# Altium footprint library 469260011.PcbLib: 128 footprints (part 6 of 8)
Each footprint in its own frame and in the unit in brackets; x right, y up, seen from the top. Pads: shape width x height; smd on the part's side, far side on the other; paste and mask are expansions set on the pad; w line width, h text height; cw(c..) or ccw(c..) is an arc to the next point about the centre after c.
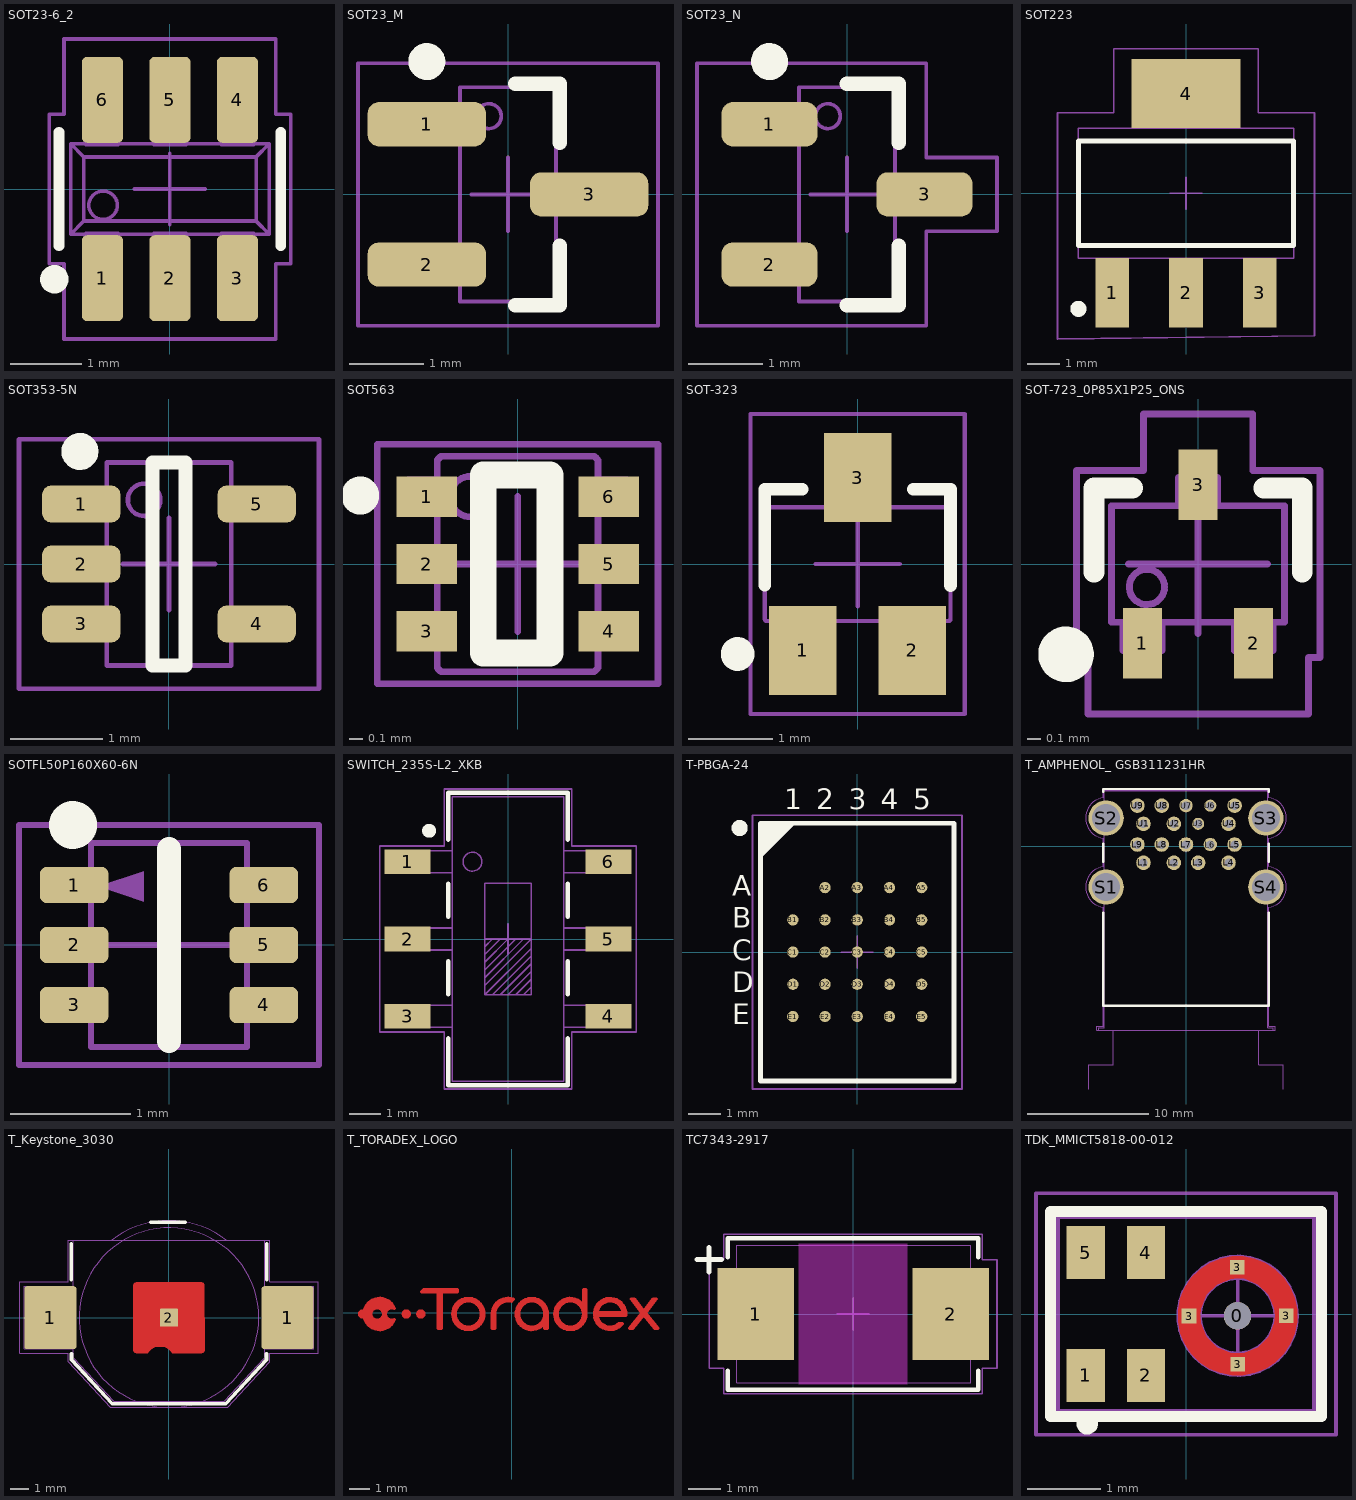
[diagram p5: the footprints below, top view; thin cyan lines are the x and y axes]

## SOT23-6_2 [mm]
pads (6):
  rrect25% 0.58x1.21 smd: 1(-0.95,-1.255) 2(0,-1.255) 3(0.95,-1.255) 4(0.95,1.255) 5(0,1.255) 6(-0.95,1.255)
Top Overlay:
  circle w0.2: c-1.626,-1.27 r0.1
  lines w0.15: -1.56,-0.8 -1.56,0.8 ; 1.56,-0.8 1.56,0.8
Top Assembly:
  circle w0.05: c-0.94,-0.229 r0.2
  lines w0.05: -1.181,-0.635 -1.397,-0.635 ; -1.181,0.635 -1.397,0.635 ; -0.724,-0.635 -0.229,-0.635 ; -0.724,0.635 -0.229,0.635 ; 0.229,-0.635 0.724,-0.635 ; 0.229,0.635 0.724,0.635 ; 1.181,-0.635 1.397,-0.635 ; 1.181,0.635 1.397,0.635 ; -1.397,-0.635 -1.397,0.635 ; -1.397,-0.635 -1.212,-0.45 ; -1.397,0.635 -1.212,0.45 ; -1.212,-0.45 -1.212,0.45 ; -1.212,-0.45 1.212,-0.45 ; -1.212,0.45 1.212,0.45 ; -1.181,-1.003 -0.724,-1.003 ; -1.181,-1.003 -1.181,-1.206 -0.724,-1.206 -0.724,-1.003 ; -1.181,-1.003 -1.181,-0.927 ; -1.181,-0.927 -1.181,-0.648 ; -1.181,-0.927 -0.724,-0.927 ; -1.181,-0.648 -0.724,-0.648 ; -1.181,-0.648 -1.181,-0.626 -0.724,-0.626 -0.724,-0.648 ; -1.181,0.66 -0.724,0.66 ; -1.181,0.66 -1.181,0.94 ; -1.181,0.66 -1.181,0.626 -0.724,0.626 -0.724,0.66 ; -1.181,0.94 -1.181,1.016 ; -1.181,0.94 -0.724,0.94 ; -1.181,1.016 -0.724,1.016 ; -1.181,1.016 -1.181,1.219 -0.724,1.219 -0.724,1.016 ; -0.724,-1.003 -0.724,-0.927 ; -0.724,-0.927 -0.724,-0.648 ; -0.724,0.66 -0.724,0.94 ; -0.724,0.94 -0.724,1.016 ; -0.229,-1.003 0.229,-1.003 ; -0.229,-1.003 -0.229,-1.206 0.229,-1.206 0.229,-1.003 ; -0.229,-1.003 -0.229,-0.927 ; -0.229,-0.927 -0.229,-0.648 ; -0.229,-0.927 0.229,-0.927 ; -0.229,-0.648 0.229,-0.648 ; -0.229,-0.648 -0.229,-0.626 0.229,-0.626 0.229,-0.648 ; -0.229,0.66 0.229,0.66 ; -0.229,0.66 -0.229,0.94 ; -0.229,0.66 -0.229,0.626 0.229,0.626 0.229,0.66 ; -0.229,0.94 -0.229,1.016 ; -0.229,0.94 0.229,0.94 ; -0.229,1.016 0.229,1.016 ; -0.229,1.016 -0.229,1.219 0.229,1.219 0.229,1.016 ; 0.229,-1.003 0.229,-0.927 ; 0.229,-0.927 0.229,-0.648 ; 0.229,0.66 0.229,0.94 ; 0.229,0.94 0.229,1.016 ; 0.724,-1.003 1.181,-1.003 ; 0.724,-1.003 0.724,-1.206 1.181,-1.206 1.181,-1.003 ; 0.724,-1.003 0.724,-0.927 ; 0.724,-0.927 0.724,-0.648 ; 0.724,-0.927 1.181,-0.927 ; 0.724,-0.648 1.181,-0.648 ; 0.724,-0.648 0.724,-0.626 1.181,-0.626 1.181,-0.648 ; 0.724,0.66 1.181,0.66 ; 0.724,0.66 0.724,0.94 ; 0.724,0.66 0.724,0.626 1.181,0.626 1.181,0.66 ; 0.724,0.94 0.724,1.016 ; 0.724,0.94 1.181,0.94 ; 0.724,1.016 1.181,1.016 ; 0.724,1.016 0.724,1.219 1.181,1.219 1.181,1.016 ; 1.181,-1.003 1.181,-0.927 ; 1.181,-0.927 1.181,-0.648 ; 1.181,0.66 1.181,0.94 ; 1.181,0.94 1.181,1.016 ; 1.212,-0.45 1.212,0.45 ; 1.212,-0.45 1.397,-0.635 ; 1.212,0.45 1.397,0.635 ; 1.397,-0.635 1.397,0.635
  text ".Designator" at -2.252,-0.226 h1
Top Courtyard:
  lines w0.05: -0.5,0 0.5,0 ; 0,-0.5 0,0.5 ; -1.7,-1.05 -1.7,1.05 -1.49,1.05 -1.49,2.11 1.49,2.11 1.49,1.05 1.7,1.05 1.7,-1.05 1.49,-1.05 1.49,-2.11 -1.49,-2.11 -1.49,-1.05 -1.7,-1.05
3D body "TPD4E001DBVR.step": height 1.45, standoff 0, extent -1.45,-1.4 1.45,1.4

## SOT23_M [mm]
height 2.5
pads (3):
  rrect50% 1.6x0.6 smd: 1(-1.1,0.95) 2(-1.1,-0.95) 3(1.1,0)
Top Overlay:
  circle w0.25: c-1.1,1.8 r0.125
  lines w0.2: 0.1,-1.5 0.7,-1.5 0.7,-0.7 ; 0.1,1.5 0.7,1.5 0.7,0.7
Top Assembly:
  circle w0.05: c-0.26,1.06 r0.169
  lines w0.05: -1.19,-1.19 -1.4,-1.19 -1.4,-0.71 -1.19,-0.71 ; -1.19,-1.19 -1.19,-0.71 ; -1.19,-1.19 -1.099,-1.19 ; -1.19,-0.71 -1.099,-0.71 ; -1.19,0.71 -1.19,1.19 ; -1.19,0.71 -1.4,0.71 -1.4,1.19 -1.19,1.19 ; -1.19,0.71 -1.099,0.71 ; -1.19,1.19 -1.099,1.19 ; -1.099,-1.19 -1.074,-1.19 ; -1.099,-1.19 -1.099,-0.71 ; -1.099,-0.71 -1.074,-0.71 ; -1.099,0.71 -1.099,1.19 ; -1.099,0.71 -1.074,0.71 ; -1.099,1.19 -1.074,1.19 ; -1.074,-1.19 -1.074,-0.71 ; -1.074,-1.19 -0.825,-1.19 ; -1.074,-0.71 -0.825,-0.71 ; -1.074,0.71 -1.074,1.19 ; -1.074,0.71 -0.825,0.71 ; -1.074,1.19 -0.825,1.19 ; -0.825,-1.19 -0.65,-1.19 ; -0.825,-1.19 -0.825,-0.71 ; -0.825,-0.71 -0.65,-0.71 ; -0.825,0.71 -0.825,1.19 ; -0.825,0.71 -0.65,0.71 ; -0.825,1.19 -0.65,1.19 ; -0.65,-1.19 -0.65,-0.71 ; -0.65,-1.19 -0.65,-1.45 0.65,-1.45 0.65,-0.24 ; -0.65,-0.71 -0.65,0.71 ; -0.65,0.71 -0.65,1.19 ; -0.65,1.19 -0.65,1.45 0.65,1.45 0.65,0.24 ; 0.65,-0.24 0.65,0.24 ; 0.65,-0.24 0.825,-0.24 ; 0.65,0.24 0.825,0.24 ; 0.825,-0.24 0.825,0.24 ; 0.825,-0.24 1.074,-0.24 ; 0.825,0.24 1.074,0.24 ; 1.074,-0.24 1.074,0.24 ; 1.074,-0.24 1.099,-0.24 ; 1.074,0.24 1.099,0.24 ; 1.099,-0.24 1.099,0.24 ; 1.099,-0.24 1.19,-0.24 ; 1.099,0.24 1.19,0.24 ; 1.19,-0.24 1.19,0.24 ; 1.19,-0.24 1.4,-0.24 1.4,0.24 1.19,0.24
  text ".Designator" at -0.226,2.252 h1
Top Courtyard:
  lines w0.05: -0.5,0 0.5,0 ; 0,-0.5 0,0.5 ; -2.032,-1.778 -2.032,1.778 2.032,1.778 2.032,-1.778 -2.032,-1.778
3D body "User Library-SOT23-3.step": height 1.3, standoff 0, extent -1.4,-1.45 1.4,1.45

## SOT23_N [mm] "SOT23, 3-Leads, Body 2.9x1.3mm, Pitch 0.95mm, Lead Span 2.3mm, IPC Medium Density"
height 1.1
pads (3):
  rrect50% 1.3x0.6 smd: 1(-1.05,0.95) 2(-1.05,-0.95) 3(1.05,0)
Top Overlay:
  circle w0.25: c-1.05,1.8 r0.125
  lines w0.2: 0,-1.5 0.7,-1.5 0.7,-0.7 ; 0,1.5 0.7,1.5 0.7,0.7
Top Assembly:
  circle w0.05: c-0.26,1.06 r0.169
  lines w0.05: -1.19,-1.19 -1.099,-1.19 ; -1.19,-1.19 -1.4,-1.19 -1.4,-0.71 -1.19,-0.71 ; -1.19,-1.19 -1.19,-0.71 ; -1.19,-0.71 -1.099,-0.71 ; -1.19,0.71 -1.099,0.71 ; -1.19,0.71 -1.4,0.71 -1.4,1.19 -1.19,1.19 ; -1.19,0.71 -1.19,1.19 ; -1.19,1.19 -1.099,1.19 ; -1.099,-1.19 -1.074,-1.19 ; -1.099,-1.19 -1.099,-0.71 ; -1.099,-0.71 -1.074,-0.71 ; -1.099,0.71 -1.074,0.71 ; -1.099,0.71 -1.099,1.19 ; -1.099,1.19 -1.074,1.19 ; -1.074,-1.19 -0.825,-1.19 ; -1.074,-1.19 -1.074,-0.71 ; -1.074,-0.71 -0.825,-0.71 ; -1.074,0.71 -0.825,0.71 ; -1.074,0.71 -1.074,1.19 ; -1.074,1.19 -0.825,1.19 ; -0.825,-1.19 -0.65,-1.19 ; -0.825,-1.19 -0.825,-0.71 ; -0.825,-0.71 -0.65,-0.71 ; -0.825,0.71 -0.65,0.71 ; -0.825,0.71 -0.825,1.19 ; -0.825,1.19 -0.65,1.19 ; -0.65,-1.19 -0.65,-1.45 0.65,-1.45 0.65,-0.24 ; -0.65,-1.19 -0.65,-0.71 ; -0.65,-0.71 -0.65,0.71 ; -0.65,0.71 -0.65,1.19 ; -0.65,1.19 -0.65,1.45 0.65,1.45 0.65,0.24 ; 0.65,-0.24 0.65,0.24 ; 0.65,-0.24 0.825,-0.24 ; 0.65,0.24 0.825,0.24 ; 0.825,-0.24 1.074,-0.24 ; 0.825,-0.24 0.825,0.24 ; 0.825,0.24 1.074,0.24 ; 1.074,-0.24 1.099,-0.24 ; 1.074,-0.24 1.074,0.24 ; 1.074,0.24 1.099,0.24 ; 1.099,-0.24 1.19,-0.24 ; 1.099,-0.24 1.099,0.24 ; 1.099,0.24 1.19,0.24 ; 1.19,-0.24 1.4,-0.24 1.4,0.24 1.19,0.24 ; 1.19,-0.24 1.19,0.24
  text ".Designator" at -0.226,2.252 h1
Top Courtyard:
  lines w0.05: -0.5,0 0.5,0 ; 0,-0.5 0,0.5 ; -2.032,-1.778 -2.032,1.778 1.072,1.778 1.072,0.5 2.032,0.5 2.032,-0.5 1.072,-0.5 1.072,-1.778 -2.032,-1.778
3D body "User Library-SOT23-3.step": height 1.3, standoff 0, extent -1.4,-1.45 1.4,1.45

## SOT223 [mm]
height 2
pads (4):
  rect 1.05x2.15 smd: 1(-2.3,-3.1) 2(0,-3.1) 3(2.3,-3.1)
  rect 3.4x2.15 smd: 4(0,3.1)
Top Overlay:
  circle w0.25: c-3.35,-3.602 r0.125
  lines w0.15: -3.35,-1.625 -3.35,1.625 3.35,1.625 3.35,-1.625 -3.35,-1.625
Top Assembly:
  lines w0.05: -2.616,-2.025 -2.616,-3.602 -2,-3.602 -2,-2.025 ; -1.45,2.025 -1.45,3.602 1.45,3.602 1.45,2.025 ; -0.316,-2.025 -0.316,-3.602 0.3,-3.602 0.3,-2.025 ; 1.984,-2.025 1.984,-3.602 2.6,-3.602 2.6,-2.025 ; -3.35,-2.025 -3.35,2.025 3.35,2.025 3.35,-2.025 -3.35,-2.025
  text ".Designator" at -2.252,-0.226 h1
Top Courtyard:
  lines w0.05: -0.5,0 0.5,0 ; 0,-0.5 0,0.5 ; -4,-4.54 -4,2.5 -2.252,2.5 -2.252,4.5 2.25,4.5 2.25,2.5 4,2.5 4,-4.44 -4,-4.54
3D body "User Library-SOT-223-2.STEP": height 1.9, standoff 0, extent -3.35,-3.602 3.35,3.602

## SOT353-5N [mm] "SOT353, SC70, 5-Leads, Body 2x1.3mm, Pitch 0.65mm, Lead Span 2.1mm, IPC Medium Density"
height 1.1
pads (5):
  rrect50% 0.85x0.4 smd: 1(-0.95,0.65) 2(-0.95,0) 3(-0.95,-0.65) 4(0.95,-0.65) 5(0.95,0.65)
Top Overlay:
  circle w0.2: c-0.965,1.219 r0.1
  lines w0.15: -0.178,-1.1 0.178,-1.1 0.178,1.1 -0.178,1.1 -0.178,-1.1
Top Assembly:
  circle w0.05: c-0.27,0.695 r0.175
  lines w0.05: -1.028,-0.8 -1.2,-0.8 -1.2,-0.5 -1.028,-0.5 ; -1.028,-0.8 -1.028,-0.5 ; -1.028,-0.8 -0.937,-0.8 ; -1.028,-0.5 -0.937,-0.5 ; -1.028,-0.15 -1.2,-0.15 -1.2,0.15 -1.028,0.15 ; -1.028,-0.15 -0.937,-0.15 ; -1.028,-0.15 -1.028,0.15 ; -1.028,0.15 -0.937,0.15 ; -1.028,0.5 -0.937,0.5 ; -1.028,0.5 -1.2,0.5 -1.2,0.8 -1.028,0.8 ; -1.028,0.5 -1.028,0.8 ; -1.028,0.8 -0.937,0.8 ; -0.937,-0.8 -0.925,-0.8 ; -0.937,-0.8 -0.937,-0.5 ; -0.937,-0.5 -0.925,-0.5 ; -0.937,-0.15 -0.937,0.15 ; -0.937,-0.15 -0.925,-0.15 ; -0.937,0.15 -0.925,0.15 ; -0.937,0.5 -0.925,0.5 ; -0.937,0.5 -0.937,0.8 ; -0.937,0.8 -0.925,0.8 ; -0.925,-0.8 -0.925,-0.5 ; -0.925,-0.8 -0.675,-0.8 ; -0.925,-0.5 -0.675,-0.5 ; -0.925,-0.15 -0.675,-0.15 ; -0.925,-0.15 -0.925,0.15 ; -0.925,0.15 -0.675,0.15 ; -0.925,0.5 -0.675,0.5 ; -0.925,0.5 -0.925,0.8 ; -0.925,0.8 -0.675,0.8 ; -0.675,-0.8 -0.675,-1.1 0.675,-1.1 0.675,-0.8 ; -0.675,-0.8 -0.675,-0.5 ; -0.675,-0.5 -0.675,-0.15 ; -0.675,-0.15 -0.675,0.15 ; -0.675,0.15 -0.675,0.5 ; -0.675,0.5 -0.675,0.8 ; -0.675,0.8 -0.675,1.1 0.675,1.1 0.675,0.8 ; 0.675,-0.8 0.925,-0.8 ; 0.675,-0.8 0.675,-0.5 ; 0.675,-0.5 0.925,-0.5 ; 0.675,-0.5 0.675,0.5 ; 0.675,0.5 0.675,0.8 ; 0.675,0.5 0.925,0.5 ; 0.675,0.8 0.925,0.8 ; 0.925,-0.8 0.937,-0.8 ; 0.925,-0.8 0.925,-0.5 ; 0.925,-0.5 0.937,-0.5 ; 0.925,0.5 0.937,0.5 ; 0.925,0.5 0.925,0.8 ; 0.925,0.8 0.937,0.8 ; 0.937,-0.8 1.028,-0.8 ; 0.937,-0.8 0.937,-0.5 ; 0.937,-0.5 1.028,-0.5 ; 0.937,0.5 1.028,0.5 ; 0.937,0.5 0.937,0.8 ; 0.937,0.8 1.028,0.8 ; 1.028,-0.8 1.2,-0.8 1.2,-0.5 1.028,-0.5 ; 1.028,-0.8 1.028,-0.5 ; 1.028,0.5 1.2,0.5 1.2,0.8 1.028,0.8 ; 1.028,0.5 1.028,0.8
  text ".Designator" at -2.252,-0.226 h1
Top Courtyard:
  lines w0.05: -0.5,0 0.5,0 ; 0,-0.5 0,0.5 ; -1.625,-1.35 -1.625,1.35 1.625,1.35 1.625,-1.35 -1.625,-1.35
3D body "User Library-SOT353-1.step": height 1.1, standoff 0, extent -1.2,-1.1 1.2,1.1

## SOT563 [mm]
height 0.6
pads (6):
  rect 0.45x0.3 smd: 1(-0.675,0.5) 2(-0.675,0) 3(-0.675,-0.5) 4(0.675,-0.5) 5(0.675,0) 6(0.675,0.5)
Top Overlay:
  circle w0.25: c-1.168,0.508 r0.016
  lines w0.2: -0.255,-0.66 -0.255,0.66 0.24,0.66 0.24,-0.66 -0.255,-0.66
Top Assembly:
  drawing of 441 lines, arcs and shapes, not listed
  text ".Designator" at -2.252,-0.226 h1
Top Courtyard:
  lines w0.05: -0.5,0 0.5,0 ; 0,-0.5 0,0.5 ; -1.041,-0.889 -1.041,0.889 1.041,0.889 1.041,-0.889 -1.041,-0.889
3D body "User Library-SOT-563_TI.STEP": height 0.59, standoff 0, extent -0.813,-0.8 0.813,0.8

## SOT-323 [mm] "SOT-323/SC-70; 3 Leads; Body 2.2 x 2.2 mm, inc. leads (LxW max)"
height 1
pads (3):
  rect 0.8x1.05 smd: 1(-0.65,-1.025) 2(0.65,-1.025) 3(0,1.025)
Top Overlay:
  circle w0.2: c-1.422,-1.067 r0.1
  lines w0.15: -1.1,-0.251 -1.1,0.887 -0.66,0.887 ; 0.66,0.887 1.1,0.887 1.1,-0.255
Top Assembly:
  lines w0.05: -0.85,-0.676 -1.075,-0.676 ; -0.85,-0.676 -1.075,-0.676 ; -0.45,-0.676 0.45,-0.676 ; 0.85,-0.676 1.075,-0.676 ; -1.1,-0.651 ccw(c-1.075,-0.651) -1.075,-0.676 ; -1.1,-0.651 ccw(c-1.075,-0.651) -1.075,-0.676 ; -1.1,-0.651 -1.1,-0.607 -1.1,0.604 -1.1,0.648 ; -1.1,0.648 cw(c-1.075,0.648) -1.075,0.673 ; -1.1,0.648 cw(c-1.075,0.648) -1.075,0.673 ; -1.075,-0.676 -1.075,-0.676 ; -1.075,0.673 -1.075,0.673 ; -1.075,0.673 -0.2,0.673 -1.075,0.673 ; 0.45,-1.099 ccw(c0.475,-1.099) 0.475,-1.124 ; 0.45,-1.099 0.45,-1.016 ; 0.45,-1.099 0.475,-1.099 ; 0.45,-1.016 0.45,-0.891 ; 0.45,-1.016 0.475,-1.016 ; 0.45,-0.891 ccw(c0.475,-0.891) 0.475,-0.916 ; 0.45,-0.891 0.45,-0.854 ; 0.45,-0.854 ccw(c0.475,-0.854) 0.475,-0.879 ; 0.45,-0.854 0.45,-0.68 0.475,-0.68 ; 0.475,-1.124 0.825,-1.124 ; 0.475,-1.124 0.475,-1.099 ; 0.475,-1.099 0.825,-1.099 ; 0.475,-1.099 0.475,-1.016 ; 0.475,-1.016 0.475,-0.916 ; 0.475,-0.916 0.475,-0.879 ; 0.475,-0.879 0.475,-0.68 ; 0.475,-0.68 0.825,-0.68 ; 0.825,-1.124 ccw(c0.825,-1.099) 0.85,-1.099 ; 0.825,-1.124 0.825,-1.099 ; 0.825,-1.099 0.825,-1.016 ; 0.825,-1.099 0.85,-1.099 ; 0.825,-1.016 0.825,-0.916 ; 0.825,-1.016 0.85,-1.016 ; 0.825,-0.916 ccw(c0.825,-0.891) 0.85,-0.891 ; 0.825,-0.916 0.825,-0.879 ; 0.825,-0.879 ccw(c0.825,-0.854) 0.85,-0.854 ; 0.825,-0.879 0.825,-0.68 ; 0.825,-0.68 0.85,-0.68 0.85,-0.854 ; 0.85,-1.099 0.85,-1.016 ; 0.85,-1.016 0.85,-0.891 ; 0.85,-0.891 0.85,-0.854 ; 1.075,-0.676 ccw(c1.075,-0.651) 1.1,-0.651 ; 1.075,-0.676 1.075,-0.676 ccw(c1.075,-0.651) 1.1,-0.651 ; 1.075,0.673 cw(c1.075,0.648) 1.1,0.648 ; 1.075,0.673 cw(c1.075,0.648) 1.1,0.648 ; 1.075,0.673 1.075,0.673 ; 1.075,0.673 0.2,0.673 1.075,0.673 ; 1.1,-0.651 1.1,-0.607 1.1,0.604 1.1,0.648 ; -0.85,-1.099 ccw(c-0.825,-1.099) -0.825,-1.124 -0.475,-1.124 ccw(c-0.475,-1.099) -0.45,-1.099 -0.45,-1.016 -0.45,-0.891 -0.45,-0.854 -0.45,-0.68 -0.475,-0.68 -0.825,-0.68 -0.85,-0.68 -0.85,-0.854 -0.85,-0.891 -0.85,-1.016 -0.85,-1.099 ; -0.2,0.676 -0.2,0.851 -0.2,0.888 -0.2,1.013 -0.2,1.096 cw(c-0.175,1.096) -0.175,1.121 0.175,1.121 cw(c0.175,1.096) 0.2,1.096 0.2,1.013 0.2,0.888 0.2,0.851 0.2,0.676 0.175,0.676 -0.175,0.676 -0.2,0.676
  text ".Designator" at -2.252,-0.226 h1
Top Courtyard:
  lines w0.05: -0.5,0 0.5,0 ; 0,-0.5 0,0.5 ; -1.27,-1.778 -1.27,1.778 1.27,1.778 1.27,-1.778 -1.27,-1.778
3D body "User Library-SOT323 (SC70-3)-1.STEP": height 1.1, standoff 0, extent -1.1,-1.123 1.1,1.123

## SOT-723_0P85X1P25_ONS [mil] "SOT-723"
height 21.65
pads (3):
  rect 11x20 smd paste+0 mask+0: 1(-15.75,-22.5) 2(15.75,-22.5) 3(0,22.5)
Top Overlay:
  circle w7.87: c-37.4,-25.59 r3.94
  lines w5.91: -29.5,-2.33 -29.5,21.5 -18.6,21.5 ; 18.6,21.5 29.5,21.5 29.5,-2.33
Top Assembly:
  circle w1.97: c-14.5,-6.5 r5
  lines w1.97: -24.5,-16.5 -24.5,16.5 24.5,16.5 24.5,-16.5 -24.5,-16.5 ; -21.25,-24.5 -10.25,-24.5 -10.25,-16.5 -21.25,-16.5 -21.25,-24.5 ; -5.5,16.5 -5.5,24.5 5.5,24.5 5.5,16.5 -5.5,16.5 ; 10.25,-24.5 21.25,-24.5 21.25,-16.5 10.25,-16.5 10.25,-24.5
  text ".Designator" at -95.8,-8.88 h39.37
Top Courtyard:
  lines w1.97: -19.68,0.01 19.69,-0.01 ; -0.01,-19.69 0.01,19.68 ; -34.5,-26.5 -31.25,-26.5 -31.25,-42.5 31.25,-42.5 31.25,-26.5 34.5,-26.5 34.5,26.5 15.5,26.5 15.5,42.5 -15.5,42.5 -15.5,26.5 -34.5,26.5 -34.5,-26.5
3D body "User Library-SOT-723.step": height 17.72, standoff -0.2, extent -24.61,-19.68 24.61,21.65

## SOTFL50P160X60-6N [mm] "SOT-563, SOT-666"
height 1.25
pads (6):
  rrect35% 0.57x0.3 smd: 1(-0.79,0.5) 2(-0.79,0) 3(-0.79,-0.5) 4(0.79,-0.5) 5(0.79,0) 6(0.79,0.5)
Top Overlay:
  circle w0.2: c-0.8,1 r0.1
  lines w0.2: 0,-0.8 0,0.8
Top 3D Body:
  lines w0.001: -0.65,-0.85 0.65,-0.85 0.65,0.85 -0.65,0.85 -0.65,-0.85
Top Assembly:
  region: -0.59,0.489 -0.209,0.616 -0.209,0.362
  lines w0.05: -0.65,-0.85 0.65,-0.85 0.65,0.85 -0.65,0.85 -0.65,-0.85
  text ".Designator" at -1.689,-0.17 h0.75
Top Courtyard:
  lines w0.05: -0.5,0 0.5,0 ; 0,-0.5 0,0.5 ; -1.25,-1 -1.25,1 1.25,1 1.25,-1 -1.25,-1
3D body "User Library-SOT-563.STEP": height 0.58, standoff 0, extent -0.813,-0.8 0.813,0.8

## SWITCH_235S-L2_XKB [mm] "Surface Mount,Right Angle 50mA DPDT 12V 12V 50mA 1?? Black SMD Slide Switches ROHS"
height 6.4
pads (6):
  rect 1.5x0.8 smd paste+0 mask+0: 1(-3.25,2.5) 2(-3.25,0) 3(-3.25,-2.5) 4(3.25,-2.5) 5(3.25,0) 6(3.25,2.5)
Top Overlay:
  circle w0.25: c-2.55,3.5 r0.1
  lines w0.15: -1.93,-3.217 -1.93,-4.724 1.93,-4.724 1.93,-3.217 ; -1.93,-1.783 -1.93,-0.717 ; -1.93,0.717 -1.93,1.783 ; -1.93,3.217 -1.93,4.724 1.93,4.724 1.93,3.217 ; 1.93,-1.783 1.93,-0.717 ; 1.93,0.717 1.93,1.783
Top Assembly:
  circle w0.05: c-1.15,2.5 r0.305
  lines w0.05: -0.751,-1.805 0.75,-0.304 ; -0.751,-1.501 0.75,0 -0.749,0 ; -0.751,-1.251 0.5,0 ; -0.75,-1.005 0.253,-0.003 ; -0.751,-0.751 0,0 ; -0.751,-0.501 -0.25,0 ; -0.75,-0.25 -0.5,0 ; -0.5,-1.803 0.751,-0.553 ; -0.253,-1.801 0.75,-0.798 ; 0,-1.803 0.751,-1.053 ; 0.25,-1.803 0.751,-1.303 ; 0.5,-1.803 0.75,-1.553 ; -3.505,-2.856 -1.803,-2.856 -1.803,-2.145 -3.505,-2.145 -3.505,-2.856 ; -3.505,-0.356 -1.803,-0.356 -1.803,0.356 -3.505,0.356 -3.505,-0.356 ; -3.505,2.145 -1.803,2.145 -1.803,2.856 -3.505,2.856 -3.505,2.145 ; -1.803,-4.597 1.803,-4.597 1.803,4.597 -1.803,4.597 -1.803,-4.597 ; -0.749,-1.803 -0.749,1.803 0.749,1.803 0.749,-1.803 -0.749,-1.803 ; 1.803,-2.856 3.505,-2.856 3.505,-2.145 1.803,-2.145 1.803,-2.856 ; 1.803,-0.356 3.505,-0.356 3.505,0.356 1.803,0.356 1.803,-0.356 ; 1.803,2.145 1.803,2.856 3.505,2.856 3.505,2.145 1.803,2.145
  text ".Designator" at -2.434,-0.226 h1
Top Courtyard:
  lines w0.05: -0.5,0 0.5,0 ; 0,-0.5 0,0.5 ; -4.15,-3.008 -2.057,-3.008 -2.057,-4.851 2.057,-4.851 2.057,-3.008 4.15,-3.008 4.15,3.008 2.057,3.008 2.057,4.851 -2.057,4.851 -2.057,3.008 -4.15,3.008 -4.15,-3.008
3D body "SS-3235S-L2.stp": height 6.55, standoff 0, extent -3.75,-4.55 3.75,4.55

## T-PBGA-24 [mm] "BGA, 25-Leads, Body 6,00x8,00mmx1,10mm, Pitch 1,00mm"
height 1.1
pads (24):
  round 0.35 smd: A2(-1,2) A3(0,2) A4(1,2) A5(2,2) B1(-2,1) B2(-1,1) B3(0,1) B4(1,1) B5(2,1) C1(-2,0) C2(-1,0) C3(0,0) C4(1,0) C5(2,0) D1(-2,-1) D2(-1,-1) D3(0,-1) D4(1,-1) D5(2,-1) E1(-2,-2) E2(-1,-2) E3(0,-2) E4(1,-2) E5(2,-2)
Top Overlay:
  circle w0.25: c-3.65,3.85 r0.125
  region: -2,4 -3,3 -3,4
  lines w0.15: -3,3 -2,4 ; -3,-4 3,-4 3,4 -3,4 -3,-4
  text "5" at 1.733,4.426 h0.64
  text "3" at -0.267,4.426 h0.64
  text "4" at 0.733,4.426 h0.64
  text "2" at -1.267,4.426 h0.64
  text "1" at -2.267,4.426 h0.64
  text "A" at -3.886,1.753 h0.64
  text "B" at -3.886,0.753 h0.64
  text "C" at -3.886,-0.247 h0.64
  text "D" at -3.886,-1.247 h0.64
  text "E" at -3.886,-2.247 h0.64
Top Assembly:
  lines w0.05: -3,-4 3,-4 3,4 -3,4 -3,-4
  text ".Designator" at -2.252,-0.226 h1
Top Courtyard:
  lines w0.05: -0.5,0 0.5,0 ; 0,-0.5 0,0.5 ; -3.25,-4.25 3.25,-4.25 3.25,4.25 -3.25,4.25 -3.25,-4.25
3D body "User Library-BGA 24 6x8.step": height 0.8, standoff -0.25, extent -3,-4 3,4

## T_AMPHENOL_ GSB311231HR [mm]
pads (22):
  round 1.2 hole 0.7: L1(-3.5,-1.35) L2(-1,-1.35) L3(1,-1.35) L4(3.5,-1.35) L5(4,0.15) L7(0,0.15) L8(-2,0.15) L9(-4,0.15) U1(-3.5,1.85) U2(-1,1.85) U4(3.5,1.85) U5(4,3.35) U8(-2,3.35) U9(-4,3.35)
  round 1.1 hole 0.7: L6(2,0.15) U7(0,3.35)
  round 2.9 hole 2.3: S1(-6.57,-3.35) S2(-6.57,2.33) S3(6.57,2.33) S4(6.57,-3.35)
  round 1 hole 0.7: U3(1,1.85) U6(2,3.35)
Top Overlay:
  lines w0.2: -6.8,-5.48 -6.8,-13.13 6.8,-13.13 6.8,-5.48 ; -6.8,-1.28 -6.8,0.22 ; -6.8,4.5 -6.8,4.72 6.8,4.72 6.8,4.5 ; 6.8,-1.28 6.8,0.22
Mechanical 1:
  lines w0.1: -8,-19.98 -8,-17.98 -6,-17.98 -6,-15.13 ; 6,-15.13 6,-17.98 8,-17.98 8,-19.98 ; -7.2,-15.13 -7.2,-14.93 -6.75,-14.93 -6.75,4.57 6.75,4.57 6.75,-14.93 7.2,-14.93 7.2,-15.13 -7.2,-15.13
Top Assembly:
  lines w0.01: -6.753,4.57 6.747,4.57 ; -6.75,4.57 -6.75,-14.93 -7.2,-14.93 -7.2,-15.13 7.2,-15.13 7.2,-14.93 6.75,-14.93 6.75,4.57
  text ".Designator" at -2.252,-0.226 h1
Top Courtyard:
  lines w0.05: -6.825,-1.655 -6.825,0.645 ; -6.825,4.011 -6.825,4.645 6.825,4.645 6.825,4.011 ; -6.824,0.65 cw(c-6.565,2.331) -6.824,4.011 ; -6.823,-1.669 ccw(c-6.565,-3.349) -6.825,-5.029 -6.825,-14.83 -7.349,-14.83 -7.349,-15.13 7.349,-15.13 7.349,-14.83 6.825,-14.83 6.825,-5.029 ccw(c6.565,-3.349) 6.823,-1.669 ; -0.5,0 0.5,0 ; 0,-0.5 0,0.5 ; 6.824,0.65 ccw(c6.565,2.331) 6.824,4.011 ; 6.825,-1.655 6.825,0.645
3D body "GSB311231HR.STEP": height 16.13, standoff -3.49, extent -7.795,-15.13 7.795,4.57

## T_Keystone_3030 [mm] "Battery Holder"
height 2.95
pads (3):
  rrect10% 2.9x3.5 smd paste+0: 1(-6.6,0) 1(6.6,0)
  rrect10% 1x1 smd paste-1000 mask+0: 2(0,0)
Top Layer:
  region: -1.782,-1.98 -1.821,-1.98 -1.894,-1.95 -1.95,-1.894 -1.98,-1.821 -1.98,-1.782 -1.98,1.782 -1.98,1.821 -1.95,1.894 -1.894,1.95 -1.821,1.98 -1.782,1.98 1.795,1.98 1.831,1.98 1.897,1.953 1.948,1.902 1.975,1.836 1.975,1.8 1.98,-1.782 1.98,-1.821 1.95,-1.894 1.894,-1.95 1.821,-1.98 1.782,-1.98 0.18,-1.98 0.18,-1.979 0.122,-1.896 -0.025,-1.756 -0.203,-1.657 -0.399,-1.606 -0.602,-1.607 -0.798,-1.658 -0.976,-1.757 -1.122,-1.897 -1.181,-1.98
Top Overlay:
  lines w0.2: -5.436,2.125 -5.436,4.108 ; -5.425,-2 -5.425,-2.342 -3.156,-4.792 3.156,-4.792 5.425,-2.342 5.425,-2 ; -1,5.308 0.9,5.308 ; 5.436,2.125 5.436,4.108
Top Solder:
  region: -4.5,0 -4.5,0.295 -4.423,0.88 -4.27,1.45 -4.045,1.995 -3.75,2.505 -3.391,2.973 -2.973,3.391 -2.505,3.75 -1.995,4.045 -1.45,4.27 -0.88,4.423 -0.295,4.5 0,4.5 0.295,4.5 0.88,4.423 1.45,4.27 1.995,4.045 2.505,3.75 2.973,3.391 3.391,2.973 3.75,2.505 4.045,1.995 4.27,1.45 4.423,0.88 4.5,0.295 4.5,0 4.5,-0.295 4.423,-0.88 4.27,-1.45 4.045,-1.995 3.75,-2.505 3.391,-2.973 2.973,-3.391 2.505,-3.75 1.995,-4.045 1.45,-4.27 0.88,-4.423 0.295,-4.5 0,-4.5 -0.295,-4.5 -0.88,-4.423 -1.45,-4.27 -1.995,-4.045 -2.505,-3.75 -2.973,-3.391 -3.391,-2.973 -3.75,-2.505 -4.045,-1.995 -4.27,-1.45 -4.423,-0.88 -4.5,-0.295
Top Assembly:
  circle w0.01: c0,0 r5
  lines w0.05: -5.325,-1.742 -8.05,-1.742 -8.05,1.758 -5.325,1.758 ; 5.325,-2.225 3.087,-4.642 -3.087,-4.642 -5.325,-2.225 -5.325,4.308 5.325,4.308 5.325,-2.217 ; 5.325,-1.742 8.05,-1.742 8.05,1.758 5.325,1.758
  text ".Designator" at -1.689,-0.17 h0.75
Top Courtyard:
  lines w0.05: -8.1,-1.992 -5.6,-1.992 ; -3.2,4.308 -5.6,4.308 -5.6,2.008 -8.3,2.008 -8.3,-1.992 -5.6,-1.992 ; -3.199,4.307 cw(c0,0.208) 3.199,4.307 ; -0.5,0 0.5,0 ; 0,-0.5 0,0.5 ; 3.2,4.308 5.6,4.308 5.6,2.008 8.3,2.008 8.3,-1.992 5.6,-1.992 5.6,-2.453 3.264,-4.992 -3.258,-4.992 -5.6,-2.455 -5.6,-1.992
3D body "CR1025 3V Cell.SLDPRT": height 2.5, standoff 0, extent -4.997,-5 4.997,4.995
3D body "Batt_Keystone_3030_eec.STEP": height 3.2, standoff 0, extent -8.051,-4.597 8.053,4.011

## T_TORADEX_LOGO [mm] "Toradex Logo in copper, no soldermask"
Top Layer:
  lines w0.15: -7.116,-0.05 -7,-0.05 ; -7.115,-0.198 cw(c-7.136,-0.05) -7.286,-0.05 cw(c-7.136,-0.05) -7.115,0.099 ; -7.044,-0.26 ccw(c-6.322,-0.05) -5.621,-0.319 ; -7.044,0.16 cw(c-6.322,-0.05) -5.621,0.22 ; -6.911,-0.118 ccw(c-7.104,-0.277) -7,-0.05 ; -6.911,0.019 cw(c-7.104,0.178) -7,-0.05 ; -6.764,-0.4 ccw(c-6.322,-0.05) -5.955,-0.477 cw(c-5.738,-0.05) -6.087,-0.379 cw(c-6.436,-0.05) -6.916,-0.05 cw(c-6.436,-0.05) -6.087,0.28 cw(c-5.738,-0.05) -5.955,0.378 ccw(c-6.322,-0.05) -6.764,0.301 ; -6.484,-0.59 ccw(c-6.436,-0.05) -6.087,-0.465 ccw(c-5.738,-0.05) -6.067,-0.481 cw(c-6.322,-0.05) -6.192,-0.533 ; -6.484,0.491 cw(c-6.436,-0.05) -6.087,0.366 cw(c-5.738,-0.05) -6.067,0.382 ccw(c-6.322,-0.05) -6.192,0.434 ; -5.636,-0.331 cw(c-5.738,-0.05) -5.636,0.232 ; 4.083,-0.046 4.702,-0.046 5.383,-0.046 ccw(c4.702,-0.05) 5.214,-0.499 ; 4.087,-0.116 4.702,-0.116 5.45,-0.116 ccw(c4.702,-0.05) 5.304,-0.499 5.127,-0.499 cw(c4.702,-0.05) 5.317,0.017 4.702,0.017 4.087,0.017 ; -7.241,-0.05 cw(c-7.136,-0.05) -7.121,0.054 ccw(c-7.104,0.178) -6.984,0.143 cw(c-6.322,-0.05) -5.732,0.305 ccw(c-5.738,-0.05) -6.087,0.015 ccw(c-6.436,-0.05) -6.087,-0.114 ccw(c-5.738,-0.05) -5.732,-0.404 cw(c-6.322,-0.05) -6.984,-0.242 ccw(c-7.104,-0.277) -7.121,-0.153 ; -7.241,-0.05 ccw(c-7.136,-0.05) -7.121,-0.153 ; -7.241,-0.05 ccw(c-7.136,-0.05) -7.121,-0.153 ; -7.178,-0.05 cw(c-7.136,-0.05) -7.13,-0.008 ccw(c-7.104,0.178) -6.924,0.126 cw(c-6.322,-0.05) -5.844,0.354 ccw(c-5.738,-0.05) -6.087,0.179 ccw(c-6.436,-0.05) -6.087,-0.278 ccw(c-5.738,-0.05) -5.844,-0.453 cw(c-6.322,-0.05) -6.924,-0.225 ccw(c-7.104,-0.277) -7.13,-0.091 cw(c-7.136,-0.05) -7.178,-0.05 ; -6.736,-0.05 ccw(c-6.436,-0.05) -6.136,-0.05 ccw(c-6.436,-0.05) -6.736,-0.05 ; -5.194,-0.05 cw(c-5.044,-0.05) -4.894,-0.05 cw(c-5.044,-0.05) -5.194,-0.05 ; -5.149,-0.05 ccw(c-5.044,-0.05) -4.939,-0.05 ccw(c-5.044,-0.05) -5.149,-0.05 ; -5.086,-0.05 cw(c-5.044,-0.05) -5.002,-0.05 cw(c-5.044,-0.05) -5.086,-0.05 ; -4.498,-0.05 cw(c-4.348,-0.05) -4.198,-0.05 cw(c-4.348,-0.05) -4.498,-0.05 ; -4.453,-0.05 ccw(c-4.348,-0.05) -4.243,-0.05 ccw(c-4.348,-0.05) -4.453,-0.05 ; -4.39,-0.05 cw(c-4.348,-0.05) -4.306,-0.05 cw(c-4.348,-0.05) -4.39,-0.05 ; -4.322,0.994 -4.218,1.125 -2.603,1.125 -2.603,0.994 -3.372,0.994 -3.372,-0.75 -3.523,-0.75 -3.523,0.994 -4.322,0.994 ; -4.192,1.057 -4.188,1.062 -2.665,1.062 -2.665,1.057 -3.434,1.057 -3.434,-0.688 -3.46,-0.688 -3.46,1.057 -4.192,1.057 ; -2.827,-0.05 cw(c-2.076,-0.05) -1.324,-0.05 cw(c-2.076,-0.05) -2.827,-0.05 ; -2.764,-0.05 cw(c-2.076,-0.05) -1.387,-0.05 cw(c-2.076,-0.05) -2.764,-0.05 ; -2.694,-0.05 cw(c-2.076,-0.05) -1.457,-0.05 cw(c-2.076,-0.05) -2.694,-0.05 ; -0.939,-0.75 -0.939,-0.05 cw(c-0.188,-0.05) 0.071,0.656 ccw(c0.958,-0.05) -0.009,0.542 ccw(c-0.188,-0.05) -0.806,-0.05 -0.806,-0.75 -0.939,-0.75 ; -0.877,-0.688 -0.877,-0.05 cw(c-0.188,-0.05) -0.032,0.621 ccw(c0.958,-0.049) -0.037,0.614 ccw(c-0.188,-0.05) -0.869,-0.05 -0.869,-0.688 -0.877,-0.688 ; 0.207,-0.05 cw(c0.958,-0.05) 1.709,-0.05 1.709,-0.75 1.576,-0.75 1.576,-0.476 cw(c0.958,-0.05) 0.207,-0.05 ; 0.269,-0.05 cw(c0.958,-0.05) 1.647,-0.05 1.647,-0.688 1.639,-0.688 1.639,-0.153 cw(c0.958,-0.05) 0.269,-0.05 ; 0.339,-0.05 cw(c0.958,-0.05) 1.576,-0.05 cw(c0.958,-0.05) 0.339,-0.05 ; 2.053,-0.05 ccw(c2.804,-0.05) 3.556,-0.05 3.556,1.125 3.423,1.125 3.423,0.377 ccw(c2.804,-0.05) 2.053,-0.05 ; 2.116,-0.05 ccw(c2.804,-0.05) 3.493,-0.05 3.493,1.062 3.485,1.062 3.485,0.054 ccw(c2.804,-0.05) 2.116,-0.05 ; 2.186,-0.05 cw(c2.804,-0.05) 3.423,-0.05 cw(c2.804,-0.05) 2.186,-0.05 ; 5.623,-0.75 6.23,0.006 5.716,0.664 5.879,0.664 6.314,0.1 6.749,0.664 6.919,0.664 6.403,0.006 6.995,-0.75 6.835,-0.75 6.314,-0.086 5.791,-0.75 5.623,-0.75 ; 5.753,-0.688 6.309,0.005 5.844,0.602 5.849,0.602 6.314,-0.002 6.78,0.602 6.79,0.602 6.323,0.006 6.866,-0.688 6.865,-0.688 6.315,0.015 5.761,-0.688 5.753,-0.688
Top Solder:
  lines w0.15: -7.116,-0.05 -7,-0.05 ; -7.115,-0.198 cw(c-7.136,-0.05) -7.286,-0.05 cw(c-7.136,-0.05) -7.115,0.099 ; -7.044,-0.26 ccw(c-6.322,-0.05) -5.621,-0.319 ; -7.044,0.16 cw(c-6.322,-0.05) -5.621,0.22 ; -6.911,-0.118 ccw(c-7.104,-0.277) -7,-0.05 ; -6.911,0.019 cw(c-7.104,0.178) -7,-0.05 ; -6.764,-0.4 ccw(c-6.322,-0.05) -5.955,-0.477 cw(c-5.738,-0.05) -6.087,-0.379 cw(c-6.436,-0.05) -6.916,-0.05 cw(c-6.436,-0.05) -6.087,0.28 cw(c-5.738,-0.05) -5.955,0.378 ccw(c-6.322,-0.05) -6.764,0.301 ; -6.484,-0.59 ccw(c-6.436,-0.05) -6.087,-0.465 ccw(c-5.738,-0.05) -6.067,-0.481 cw(c-6.322,-0.05) -6.192,-0.533 ; -6.484,0.491 cw(c-6.436,-0.05) -6.087,0.366 cw(c-5.738,-0.05) -6.067,0.382 ccw(c-6.322,-0.05) -6.192,0.434 ; -5.636,-0.331 cw(c-5.738,-0.05) -5.636,0.232 ; 4.083,-0.046 4.702,-0.046 5.383,-0.046 ccw(c4.702,-0.05) 5.214,-0.499 ; 4.087,-0.116 4.702,-0.116 5.45,-0.116 ccw(c4.702,-0.05) 5.304,-0.499 5.127,-0.499 cw(c4.702,-0.05) 5.317,0.017 4.702,0.017 4.087,0.017 ; -7.241,-0.05 cw(c-7.136,-0.05) -7.121,0.054 ccw(c-7.104,0.178) -6.984,0.143 cw(c-6.322,-0.05) -5.732,0.305 ccw(c-5.738,-0.05) -6.087,0.015 ccw(c-6.436,-0.05) -6.087,-0.114 ccw(c-5.738,-0.05) -5.732,-0.404 cw(c-6.322,-0.05) -6.984,-0.242 ccw(c-7.104,-0.277) -7.121,-0.153 ; -7.241,-0.05 ccw(c-7.136,-0.05) -7.121,-0.153 ; -7.241,-0.05 ccw(c-7.136,-0.05) -7.121,-0.153 ; -7.178,-0.05 cw(c-7.136,-0.05) -7.13,-0.008 ccw(c-7.104,0.178) -6.924,0.126 cw(c-6.322,-0.05) -5.844,0.354 ccw(c-5.738,-0.05) -6.087,0.179 ccw(c-6.436,-0.05) -6.087,-0.278 ccw(c-5.738,-0.05) -5.844,-0.453 cw(c-6.322,-0.05) -6.924,-0.225 ccw(c-7.104,-0.277) -7.13,-0.091 cw(c-7.136,-0.05) -7.178,-0.05 ; -6.736,-0.05 cw(c-6.436,-0.05) -6.136,-0.05 cw(c-6.436,-0.05) -6.736,-0.05 ; -5.194,-0.05 cw(c-5.044,-0.05) -4.894,-0.05 cw(c-5.044,-0.05) -5.194,-0.05 ; -5.149,-0.05 cw(c-5.044,-0.05) -4.939,-0.05 cw(c-5.044,-0.05) -5.149,-0.05 ; -5.086,-0.05 cw(c-5.044,-0.05) -5.002,-0.05 cw(c-5.044,-0.05) -5.086,-0.05 ; -4.498,-0.05 ccw(c-4.348,-0.05) -4.198,-0.05 ccw(c-4.348,-0.05) -4.498,-0.05 ; -4.453,-0.05 cw(c-4.348,-0.05) -4.243,-0.05 cw(c-4.348,-0.05) -4.453,-0.05 ; -4.39,-0.05 cw(c-4.348,-0.05) -4.306,-0.05 cw(c-4.348,-0.05) -4.39,-0.05 ; -4.322,0.994 -4.218,1.125 -2.603,1.125 -2.603,0.994 -3.372,0.994 -3.372,-0.75 -3.523,-0.75 -3.523,0.994 -4.322,0.994 ; -4.192,1.057 -4.188,1.062 -2.665,1.062 -2.665,1.057 -3.434,1.057 -3.434,-0.688 -3.46,-0.688 -3.46,1.057 -4.192,1.057 ; -2.827,-0.05 cw(c-2.076,-0.05) -1.324,-0.05 cw(c-2.076,-0.05) -2.827,-0.05 ; -2.764,-0.05 cw(c-2.076,-0.05) -1.387,-0.05 cw(c-2.076,-0.05) -2.764,-0.05 ; -2.694,-0.05 cw(c-2.076,-0.05) -1.457,-0.05 cw(c-2.076,-0.05) -2.694,-0.05 ; -0.939,-0.75 -0.939,-0.05 cw(c-0.188,-0.05) 0.071,0.656 ccw(c0.958,-0.05) -0.009,0.542 ccw(c-0.188,-0.05) -0.806,-0.05 -0.806,-0.75 -0.939,-0.75 ; -0.877,-0.688 -0.877,-0.05 cw(c-0.188,-0.05) -0.032,0.621 ccw(c0.958,-0.049) -0.037,0.614 ccw(c-0.188,-0.05) -0.869,-0.05 -0.869,-0.688 -0.877,-0.688 ; 0.207,-0.05 cw(c0.958,-0.05) 1.709,-0.05 1.709,-0.75 1.576,-0.75 1.576,-0.476 cw(c0.958,-0.05) 0.207,-0.05 ; 0.269,-0.05 cw(c0.958,-0.05) 1.647,-0.05 1.647,-0.688 1.639,-0.688 1.639,-0.153 cw(c0.958,-0.05) 0.269,-0.05 ; 0.339,-0.05 cw(c0.958,-0.05) 1.576,-0.05 cw(c0.958,-0.05) 0.339,-0.05 ; 2.053,-0.05 ccw(c2.804,-0.05) 3.556,-0.05 3.556,1.125 3.423,1.125 3.423,0.377 ccw(c2.804,-0.05) 2.053,-0.05 ; 2.116,-0.05 ccw(c2.804,-0.05) 3.493,-0.05 3.493,1.062 3.485,1.062 3.485,0.054 ccw(c2.804,-0.05) 2.116,-0.05 ; 2.186,-0.05 ccw(c2.804,-0.05) 3.423,-0.05 ccw(c2.804,-0.05) 2.186,-0.05 ; 5.623,-0.75 6.23,0.006 5.716,0.664 5.879,0.664 6.314,0.1 6.749,0.664 6.919,0.664 6.403,0.006 6.995,-0.75 6.835,-0.75 6.314,-0.086 5.791,-0.75 5.623,-0.75 ; 5.753,-0.688 6.309,0.005 5.844,0.602 5.849,0.602 6.314,-0.002 6.78,0.602 6.79,0.602 6.323,0.006 6.866,-0.688 6.865,-0.688 6.315,0.015 5.761,-0.688 5.753,-0.688

## TC7343-2917 [mil] "Capacitor, SM Tantalum; Body 7.3 x 4.3 mm (LxW typ)"
height 153.54
pads (2):
  rect 94.5x114 smd paste+0 mask+0: 1(-120.25,0) 2(120.25,0)
Top Layer keep-out:
  region: -67,-86.5 -67,86.5 67,86.5 67,-86.5
Top Overlay:
  lines w5.91: -154.5,-70.1 -154.5,-93.5 154.5,-93.5 154.5,-70.1 ; -154.5,70.1 -154.5,93.5 154.5,93.5 154.5,70.1
  lines w6: -192.5,67 -162.5,67 ; -177.5,52 -177.5,82
Top Assembly:
  lines w1: -143.7,-84.65 -143.7,84.65 145,84.65 145,-84.65 -143.7,-84.65
  lines w1.97: -135.25,0 -105.25,0 ; -120.25,-15 -120.25,15
  text ".Designator" at -88.67,-8.9 h39.37
Top Courtyard:
  lines w1.97: -19.68,0 19.69,0 ; 0,-19.68 0,19.68 ; -177.5,-67 -159.5,-67 -159.5,-98.5 159.5,-98.5 159.5,-67 177.5,-67 177.5,67 159.5,67 159.5,98.5 -159.5,98.5 -159.5,67 -177.5,67 -177.5,-67
3D body "User Library-CAP_TANT_7343-40.step": height 157.48, standoff 0, extent -149.61,-90.55 149.61,90.55

## TDK_MMICT5818-00-012 [mm]
height 3
pads (9):
  round 0.375 hole 0.375 unplated: 0(0.704,-0.025)
  rect 0.522x0.725 smd: 1(-1.369,-0.837) 2(-0.547,-0.837) 4(-0.547,0.838) 5(-1.369,0.838)
  rect 0.2x0.2 smd paste-0.508 mask+0: 3(0.041,-0.027) 3(0.702,0.639) 3(0.708,-0.689) 3(1.369,-0.022)
Top Layer:
  region: 1.518,-0.025 1.518,-0.105 1.486,-0.262 1.425,-0.41 1.336,-0.543 1.223,-0.656 1.09,-0.745 0.942,-0.806 0.785,-0.837 0.705,-0.837 0.705,-0.538 0.805,-0.528 0.99,-0.452 1.132,-0.31 1.209,-0.125 1.218,-0.025
  region: 0.704,0.787 0.784,0.788 0.941,0.757 1.089,0.695 1.222,0.607 1.336,0.493 1.425,0.36 1.486,0.212 1.518,0.055 1.518,-0.025 1.218,-0.025 1.208,0.075 1.131,0.261 0.989,0.402 0.804,0.479 0.704,0.488
  region: 0.705,-0.837 0.625,-0.837 0.468,-0.806 0.32,-0.745 0.187,-0.656 0.074,-0.543 -0.015,-0.41 -0.076,-0.262 -0.107,-0.105 -0.107,-0.025 0.192,-0.025 0.202,-0.125 0.278,-0.31 0.42,-0.452 0.605,-0.528 0.705,-0.538
  region: -0.107,-0.025 -0.107,0.055 -0.076,0.212 -0.015,0.36 0.074,0.493 0.187,0.606 0.32,0.695 0.468,0.756 0.625,0.788 0.705,0.788 0.705,0.488 0.605,0.478 0.42,0.402 0.278,0.26 0.202,0.075 0.192,-0.025
Top Overlay:
  circle w0.15: c-1.35,-1.5 r0.072
  lines w0.15: -1.85,-1.4 1.85,-1.4 1.85,1.4 -1.85,1.4 -1.85,-1.4
Top Paste:
  region: 1.517,-0.082 1.512,-0.155 1.476,-0.296 1.415,-0.428 1.332,-0.547 1.229,-0.65 1.109,-0.733 0.976,-0.793 0.835,-0.829 0.763,-0.834 0.763,-0.533 0.847,-0.517 1.003,-0.442 1.125,-0.321 1.2,-0.167 1.217,-0.082
  region: 0.763,0.787 0.835,0.782 0.976,0.746 1.108,0.685 1.228,0.602 1.33,0.499 1.413,0.379 1.473,0.246 1.509,0.105 1.514,0.033 1.213,0.033 1.197,0.117 1.123,0.272 1.002,0.394 0.847,0.47 0.763,0.487
  region: 0.648,-0.837 0.575,-0.832 0.434,-0.795 0.302,-0.735 0.182,-0.651 0.08,-0.548 -0.003,-0.429 -0.063,-0.296 -0.099,-0.155 -0.104,-0.082 0.197,-0.082 0.213,-0.167 0.287,-0.322 0.409,-0.444 0.563,-0.519 0.648,-0.536
  region: -0.107,0.033 -0.102,0.105 -0.066,0.246 -0.005,0.379 0.078,0.498 0.181,0.601 0.301,0.683 0.434,0.744 0.575,0.779 0.647,0.784 0.647,0.484 0.563,0.467 0.408,0.393 0.286,0.272 0.211,0.117 0.193,0.033
Top Solder:
  region: 1.519,-0.025 1.519,-0.105 1.488,-0.262 1.426,-0.41 1.337,-0.543 1.224,-0.656 1.091,-0.745 0.943,-0.806 0.786,-0.837 0.706,-0.837 0.706,-0.538 0.806,-0.528 0.991,-0.451 1.133,-0.31 1.21,-0.125 1.22,-0.025
  region: 0.706,0.788 0.786,0.788 0.943,0.757 1.091,0.695 1.224,0.606 1.337,0.493 1.426,0.36 1.488,0.212 1.519,0.055 1.519,-0.025 1.219,-0.025 1.209,0.075 1.133,0.26 0.991,0.402 0.806,0.479 0.706,0.489
  region: 0.706,-0.837 0.626,-0.837 0.469,-0.806 0.321,-0.745 0.188,-0.656 0.075,-0.543 -0.014,-0.41 -0.075,-0.262 -0.106,-0.105 -0.106,-0.025 0.193,-0.025 0.203,-0.125 0.28,-0.31 0.421,-0.451 0.606,-0.528 0.706,-0.538
  region: -0.106,-0.025 -0.106,0.055 -0.075,0.212 -0.014,0.36 0.075,0.493 0.188,0.606 0.321,0.695 0.469,0.757 0.626,0.788 0.706,0.788 0.706,0.488 0.606,0.478 0.421,0.402 0.279,0.26 0.203,0.075 0.193,-0.025
Top Assembly:
  circle w0.05: c0.705,-0.025 r0.813
  circle w0.05: c0.705,-0.025 r0.513
  circle w0.05: c-1.369,-0.837 r0.2
  lines w0.05: -0.107,-0.025 1.518,-0.025 ; 0.705,-0.837 0.705,0.788 ; -1.75,-1.325 1.75,-1.325 1.75,1.325 -1.75,1.325 -1.75,-1.325
Top Courtyard:
  lines w0.05: -2.05,-1.65 2.05,-1.65 2.05,1.65 -2.05,1.65 -2.05,-1.65
3D body "T5838--3DModel-STEP-510211.STEP": height 0.98, standoff 0, extent -1.75,-1.325 1.75,1.325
